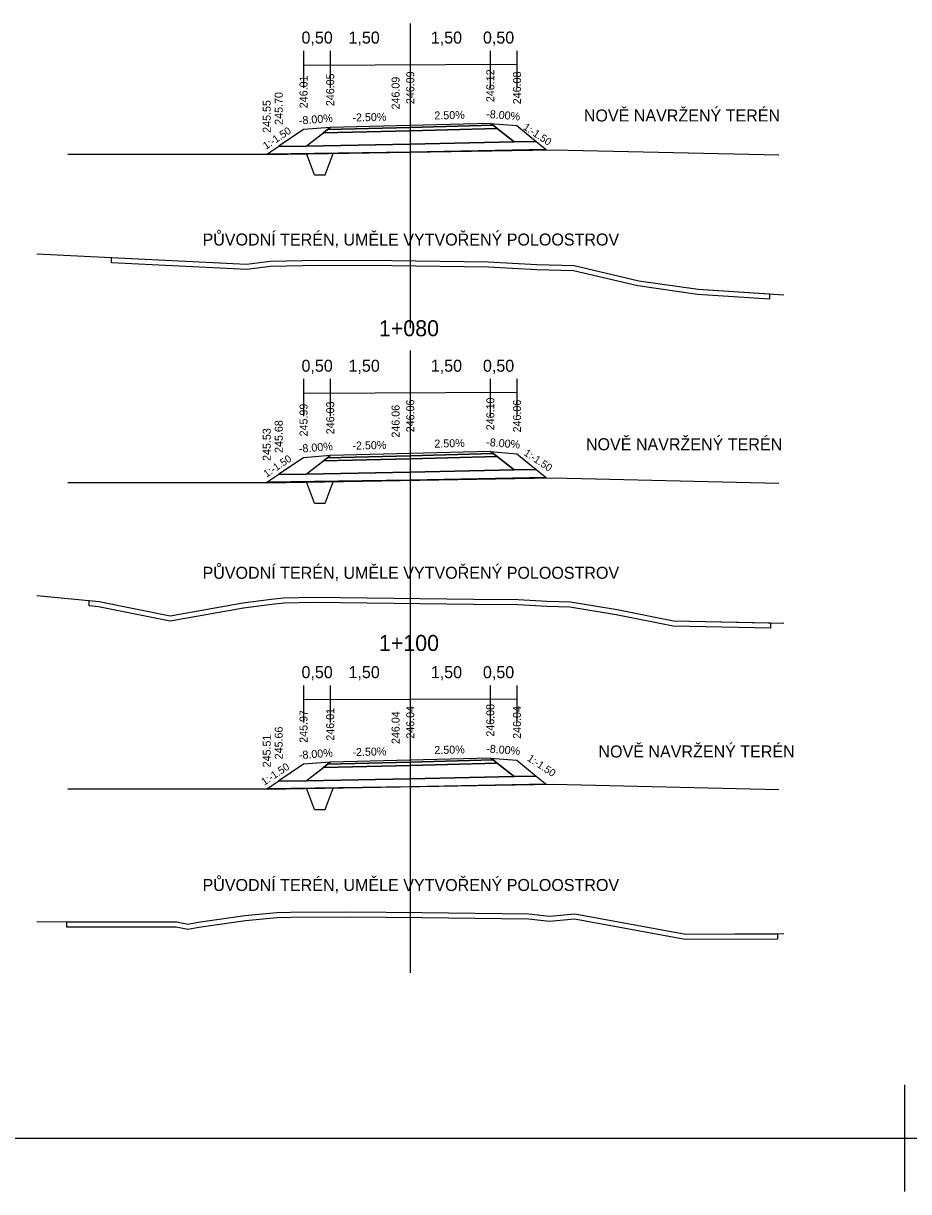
# Model space of a CAD drawing. Extents: x -552501 to -552394, y -1029983 to -1029892.
# Drawn here: x -552453.26 to -552436.67, y -1029983.45 to -1029961.55 of the extents above; entities that cross this region are included whole.
import ezdxf

# ---------------------------------------------------------------- set-up
doc = ezdxf.new("R2010")
doc.units = 0
for name, color, linetype in [('1', 7, 'Continuous'), ('16', 7, 'Continuous'), ('60', 7, 'Continuous'), ('9', 7, 'Continuous'), ('FORMATY', 7, 'Continuous'), ('Implicitní', 7, 'Continuous'), ('rámeček', 7, 'Continuous')]:
    doc.layers.add(name, color=color, linetype=linetype)

msp = doc.modelspace()

# ---------------------------------------------------------------- linework, layer by layer
for p, q in [((-552448.693, -1029964.007), (-552452.429, -1029964.007)), ((-552447.81, -1029964.389), (-552447.96, -1029963.989)), ((-552447.61, -1029964.389), (-552447.46, -1029963.989)), ((-552447.81, -1029964.389), (-552447.61, -1029964.389)), ((-552448.693, -1029970.159), (-552452.429, -1029970.159)), ((-552447.81, -1029970.542), (-552447.96, -1029970.142)), ((-552447.61, -1029970.542), (-552447.46, -1029970.142)), ((-552447.81, -1029970.542), (-552447.61, -1029970.542)), ((-552448.693, -1029975.904), (-552452.429, -1029975.904)), ((-552447.81, -1029976.286), (-552447.96, -1029975.886)), ((-552447.61, -1029976.286), (-552447.46, -1029975.886)), ((-552447.81, -1029976.286), (-552447.61, -1029976.286))]:
    msp.add_line(p, q)
for points in [[(-552447.514, -1029963.5), (-552448.014, -1029963.54), (-552448.479, -1029963.85), (-552447.965, -1029963.85)], [(-552446.015, -1029963.502), (-552447.565, -1029963.54), (-552447.643, -1029963.6), (-552446.015, -1029963.562), (-552444.386, -1029963.519), (-552444.463, -1029963.459), (-552446.015, -1029963.502), (-552444.463, -1029963.459), (-552444.514, -1029963.425), (-552446.014, -1029963.462), (-552447.514, -1029963.5), (-552447.565, -1029963.54)], [(-552447.643, -1029963.6), (-552447.565, -1029963.54), (-552446.015, -1029963.502), (-552444.463, -1029963.459), (-552444.386, -1029963.519), (-552446.015, -1029963.562)], [(-552444.514, -1029963.425), (-552444.014, -1029963.465), (-552443.653, -1029963.762), (-552444.064, -1029963.769), (-552444.386, -1029963.519), (-552444.463, -1029963.459)], [(-552447.965, -1029963.85), (-552447.643, -1029963.6), (-552446.015, -1029963.562), (-552444.386, -1029963.519), (-552444.064, -1029963.769), (-552446.015, -1029963.812)], [(-552448.704, -1029964), (-552448.479, -1029963.85), (-552447.965, -1029963.85), (-552446.015, -1029963.812), (-552444.064, -1029963.769), (-552443.653, -1029963.762), (-552443.468, -1029963.912), (-552446.015, -1029963.962)], [(-552451.613, -1029965.939), (-552449.082, -1029966.062), (-552448.639, -1029966.007), (-552447.73, -1029965.99), (-552446.357, -1029965.997), (-552444.552, -1029966.019), (-552443.641, -1029966.068), (-552442.943, -1029966.087), (-552441.731, -1029966.372), (-552440.619, -1029966.533), (-552439.28, -1029966.621), (-552439.28, -1029966.721), (-552440.63, -1029966.633), (-552441.75, -1029966.47), (-552442.956, -1029966.187), (-552443.645, -1029966.168), (-552444.555, -1029966.119), (-552446.358, -1029966.097), (-552447.729, -1029966.09), (-552448.632, -1029966.107), (-552449.078, -1029966.163), (-552451.613, -1029966.039)], [(-552446.015, -1029969.654), (-552447.565, -1029969.692), (-552447.643, -1029969.752), (-552446.015, -1029969.714), (-552444.386, -1029969.671), (-552444.463, -1029969.611), (-552446.015, -1029969.654), (-552444.463, -1029969.611), (-552444.514, -1029969.577), (-552446.014, -1029969.614), (-552447.514, -1029969.652), (-552447.565, -1029969.692)], [(-552447.643, -1029969.752), (-552447.565, -1029969.692), (-552446.015, -1029969.654), (-552444.463, -1029969.611), (-552444.386, -1029969.671), (-552446.015, -1029969.714)], [(-552444.514, -1029969.577), (-552444.014, -1029969.617), (-552443.653, -1029969.915), (-552444.064, -1029969.921), (-552444.386, -1029969.671), (-552444.463, -1029969.611)], [(-552447.514, -1029969.652), (-552448.014, -1029969.692), (-552448.479, -1029970.002), (-552447.965, -1029970.002)], [(-552447.965, -1029970.002), (-552447.643, -1029969.752), (-552446.015, -1029969.714), (-552444.386, -1029969.671), (-552444.064, -1029969.921), (-552446.015, -1029969.964)], [(-552448.704, -1029970.152), (-552448.479, -1029970.002), (-552447.965, -1029970.002), (-552446.015, -1029969.964), (-552444.064, -1029969.921), (-552443.653, -1029969.915), (-552443.468, -1029970.065), (-552446.015, -1029970.114)], [(-552452.031, -1029972.37), (-552451.844, -1029972.388), (-552450.512, -1029972.656), (-552449.154, -1029972.412), (-552448.62, -1029972.345), (-552448.388, -1029972.316), (-552447.82, -1029972.306), (-552444.827, -1029972.344), (-552443.994, -1029972.349), (-552443.446, -1029972.378), (-552443.012, -1029972.39), (-552442.135, -1029972.537), (-552441.078, -1029972.748), (-552439.262, -1029972.785), (-552439.262, -1029972.885), (-552441.089, -1029972.848), (-552442.154, -1029972.636), (-552443.022, -1029972.49), (-552443.45, -1029972.478), (-552443.997, -1029972.449), (-552444.827, -1029972.444), (-552447.82, -1029972.406), (-552448.38, -1029972.416), (-552448.608, -1029972.444), (-552449.139, -1029972.511), (-552450.513, -1029972.758), (-552451.859, -1029972.487), (-552452.031, -1029972.471)], [(-552446.015, -1029975.399), (-552447.565, -1029975.436), (-552447.643, -1029975.496), (-552446.015, -1029975.459), (-552444.386, -1029975.415), (-552444.463, -1029975.355), (-552446.015, -1029975.399), (-552444.463, -1029975.355), (-552444.514, -1029975.321), (-552446.014, -1029975.359), (-552447.514, -1029975.396), (-552447.565, -1029975.436)], [(-552444.514, -1029975.321), (-552444.014, -1029975.361), (-552443.653, -1029975.659), (-552444.064, -1029975.665), (-552444.386, -1029975.415), (-552444.463, -1029975.355)], [(-552447.514, -1029975.396), (-552448.014, -1029975.436), (-552448.479, -1029975.746), (-552447.965, -1029975.746)], [(-552447.965, -1029975.746), (-552447.643, -1029975.496), (-552446.015, -1029975.459), (-552444.386, -1029975.415), (-552444.064, -1029975.665), (-552446.015, -1029975.709)], [(-552447.643, -1029975.496), (-552447.565, -1029975.436), (-552446.015, -1029975.399), (-552444.463, -1029975.355), (-552444.386, -1029975.415), (-552446.015, -1029975.459)], [(-552448.704, -1029975.896), (-552448.479, -1029975.746), (-552447.965, -1029975.746), (-552446.015, -1029975.709), (-552444.064, -1029975.665), (-552443.653, -1029975.659), (-552443.468, -1029975.809), (-552446.015, -1029975.859)], [(-552452.448, -1029978.392), (-552452.126, -1029978.395), (-552450.39, -1029978.394), (-552450.181, -1029978.434), (-552449.991, -1029978.399), (-552449.112, -1029978.276), (-552448.515, -1029978.22), (-552448.257, -1029978.208), (-552447.133, -1029978.204), (-552445.799, -1029978.219), (-552443.794, -1029978.244), (-552443.406, -1029978.283), (-552442.931, -1029978.244), (-552440.853, -1029978.626), (-552439.135, -1029978.614), (-552439.135, -1029978.714), (-552440.862, -1029978.726), (-552442.936, -1029978.345), (-552443.407, -1029978.384), (-552443.8, -1029978.344), (-552445.8, -1029978.319), (-552447.133, -1029978.304), (-552448.254, -1029978.308), (-552448.508, -1029978.32), (-552449.1, -1029978.375), (-552449.975, -1029978.498), (-552450.181, -1029978.535), (-552450.4, -1029978.494), (-552452.126, -1029978.495), (-552452.448, -1029978.492)]]:
    msp.add_lwpolyline(points, close=True)
for points in [[(-552448.693, -1029964.007), (-552443.336, -1029963.917), (-552439.11, -1029964.014)], [(-552453.014, -1029965.871), (-552449.082, -1029966.062), (-552448.639, -1029966.007), (-552447.73, -1029965.99), (-552446.357, -1029965.997), (-552444.552, -1029966.019), (-552443.641, -1029966.068), (-552442.943, -1029966.087), (-552441.731, -1029966.372), (-552440.619, -1029966.533), (-552439.014, -1029966.638)], [(-552448.693, -1029970.159), (-552443.336, -1029970.07), (-552439.11, -1029970.166)], [(-552453.014, -1029972.277), (-552451.844, -1029972.388), (-552450.512, -1029972.656), (-552449.154, -1029972.412), (-552448.62, -1029972.345), (-552448.388, -1029972.316), (-552447.82, -1029972.306), (-552444.827, -1029972.344), (-552443.994, -1029972.349), (-552443.446, -1029972.378), (-552443.012, -1029972.39), (-552442.135, -1029972.537), (-552441.078, -1029972.748), (-552439.014, -1029972.79)], [(-552448.693, -1029975.904), (-552443.336, -1029975.814), (-552439.11, -1029975.911)], [(-552453.014, -1029978.388), (-552452.126, -1029978.395), (-552450.39, -1029978.394), (-552450.181, -1029978.434), (-552449.991, -1029978.399), (-552449.112, -1029978.276), (-552448.515, -1029978.22), (-552448.257, -1029978.208), (-552447.133, -1029978.204), (-552445.799, -1029978.219), (-552443.794, -1029978.244), (-552443.406, -1029978.283), (-552442.931, -1029978.244), (-552440.853, -1029978.626), (-552439.014, -1029978.613)]]:
    msp.add_lwpolyline(points)
at = {"layer": '60'}
for p, q in [((-552446.014, -1029961.548), (-552446.014, -1029967.264)), ((-552446.014, -1029967.679), (-552446.014, -1029973.487)), ((-552446.014, -1029973.402), (-552446.014, -1029979.35))]:
    msp.add_line(p, q, dxfattribs=at)
at = {"layer": '9'}
for p, q in [((-552448.015, -1029962.062), (-552448.015, -1029962.76)), ((-552447.515, -1029962.062), (-552447.515, -1029962.76)), ((-552446.015, -1029962.062), (-552446.015, -1029963.562)), ((-552444.515, -1029962.062), (-552444.515, -1029962.76)), ((-552444.015, -1029962.062), (-552444.015, -1029962.76)), ((-552448.015, -1029968.214), (-552448.015, -1029968.912)), ((-552447.515, -1029968.214), (-552447.515, -1029968.912)), ((-552446.015, -1029968.214), (-552446.015, -1029969.714)), ((-552444.515, -1029968.214), (-552444.515, -1029968.912)), ((-552444.015, -1029968.214), (-552444.015, -1029968.912)), ((-552448.015, -1029973.959), (-552448.015, -1029974.657)), ((-552447.515, -1029973.959), (-552447.515, -1029974.657)), ((-552446.015, -1029973.959), (-552446.015, -1029975.459)), ((-552444.515, -1029973.959), (-552444.515, -1029974.657)), ((-552444.015, -1029973.959), (-552444.015, -1029974.657))]:
    msp.add_line(p, q, dxfattribs=at)
at = {"layer": 'FORMATY'}
for p, q in [((-552436.755, -1029981.45), (-552436.755, -1029983.45)), ((-552437.755, -1029982.45), (-552435.755, -1029982.45))]:
    msp.add_line(p, q, dxfattribs=at)
at = {"layer": 'Implicitní'}
for p, q in [((-552448.005, -1029962.33), (-552444.015, -1029962.312)), ((-552448.005, -1029968.482), (-552444.015, -1029968.464)), ((-552448.005, -1029974.226), (-552444.015, -1029974.209))]:
    msp.add_line(p, q, dxfattribs=at)
at = {"layer": 'rámeček'}
for p, q in [((-552436.755, -1029981.95), (-552436.755, -1029982.45)), ((-552499.755, -1029982.45), (-552436.755, -1029982.45)), ((-552499.755, -1029982.45), (-552415.755, -1029982.45)), ((-552499.755, -1029982.45), (-552415.755, -1029982.45))]:
    msp.add_line(p, q, dxfattribs=at)

# ---------------------------------------------------------------- texts
for rotation, p in [(33.6902, (-552448.717, -1029963.919)), (326.3098, (-552443.911, -1029963.524)), (326.3098, (-552443.898, -1029969.634)), (33.6902, (-552448.707, -1029970.067)), (326.3098, (-552443.833, -1029975.359)), (33.6902, (-552448.749, -1029975.842))]:
    msp.add_text('1:-1.50', height=0.14, rotation=rotation).set_placement(p)
at = {"layer": '1'}
for s, p in [('1+080', (-552446.602, -1029967.414)), ('1+100', (-552446.602, -1029973.314))]:
    msp.add_text(s, height=0.3, dxfattribs=at).set_placement(p)
at = {"layer": '16'}
for s, p in [('0,50', (-552448.052, -1029961.927)), ('1,50', (-552447.171, -1029961.927)), ('1,50', (-552445.629, -1029961.927)), ('0,50', (-552444.652, -1029961.927)), ('NOVĚ NAVRŽENÝ TERÉN', (-552442.761, -1029963.388)), ('PŮVODNÍ TERÉN, UMĚLE VYTVOŘENÝ POLOOSTROV', (-552449.907, -1029965.713)), ('0,50', (-552448.052, -1029968.079)), ('1,50', (-552447.171, -1029968.079)), ('1,50', (-552445.629, -1029968.079)), ('0,50', (-552444.652, -1029968.079)), ('NOVĚ NAVRŽENÝ TERÉN', (-552442.722, -1029969.551)), ('PŮVODNÍ TERÉN, UMĚLE VYTVOŘENÝ POLOOSTROV', (-552449.907, -1029971.961)), ('0,50', (-552448.052, -1029973.824)), ('1,50', (-552447.171, -1029973.824)), ('1,50', (-552445.629, -1029973.824)), ('0,50', (-552444.652, -1029973.824)), ('NOVĚ NAVRŽENÝ TERÉN', (-552442.487, -1029975.311)), ('PŮVODNÍ TERÉN, UMĚLE VYTVOŘENÝ POLOOSTROV', (-552449.907, -1029977.814))]:
    msp.add_text(s, height=0.225, dxfattribs=at).set_placement(p)
for s, rotation, p in [('246.01', 90, (-552447.939, -1029963.14)), ('246.05', 90, (-552447.439, -1029963.1)), ('246.09', 90, (-552446.214, -1029963.162)), ('246.09', 90, (-552445.939, -1029963.062)), ('246.12', 90, (-552444.439, -1029963.025)), ('246.08', 90, (-552443.939, -1029963.065)), ('245.55', 90, (-552448.629, -1029963.6)), ('245.70', 90, (-552448.404, -1029963.45)), ('-8.00%', 4.5739, (-552448.095, -1029963.446)), ('-2.50%', 1.4321, (-552447.096, -1029963.389)), ('2.50%', 1.4321, (-552445.561, -1029963.351)), ('-8.00%', 355.4261, (-552444.595, -1029963.318)), ('245.99', 90, (-552447.939, -1029969.292)), ('246.03', 90, (-552447.439, -1029969.252)), ('246.06', 90, (-552446.214, -1029969.314)), ('246.06', 90, (-552445.939, -1029969.214)), ('246.10', 90, (-552444.439, -1029969.177)), ('246.06', 90, (-552443.939, -1029969.217)), ('245.53', 90, (-552448.629, -1029969.752)), ('245.68', 90, (-552448.404, -1029969.602)), ('-8.00%', 4.5739, (-552448.095, -1029969.598)), ('-2.50%', 1.4321, (-552447.096, -1029969.541)), ('2.50%', 1.4321, (-552445.561, -1029969.503)), ('-8.00%', 355.4261, (-552444.595, -1029969.47)), ('245.97', 90, (-552447.939, -1029975.036)), ('246.01', 90, (-552447.439, -1029974.996)), ('246.04', 90, (-552445.939, -1029974.959)), ('246.08', 90, (-552444.439, -1029974.921)), ('246.04', 90, (-552443.939, -1029974.961)), ('246.04', 90, (-552446.214, -1029975.059)), ('245.66', 90, (-552448.404, -1029975.346)), ('245.51', 90, (-552448.629, -1029975.496)), ('2.50%', 1.4321, (-552445.561, -1029975.248)), ('-8.00%', 355.4261, (-552444.595, -1029975.215)), ('-8.00%', 4.5739, (-552448.095, -1029975.343)), ('-2.50%', 1.4321, (-552447.096, -1029975.286))]:
    msp.add_text(s, height=0.15, rotation=rotation, dxfattribs=at).set_placement(p)

doc.saveas('drawing.dxf')
